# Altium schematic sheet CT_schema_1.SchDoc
size 486 x 344 mm
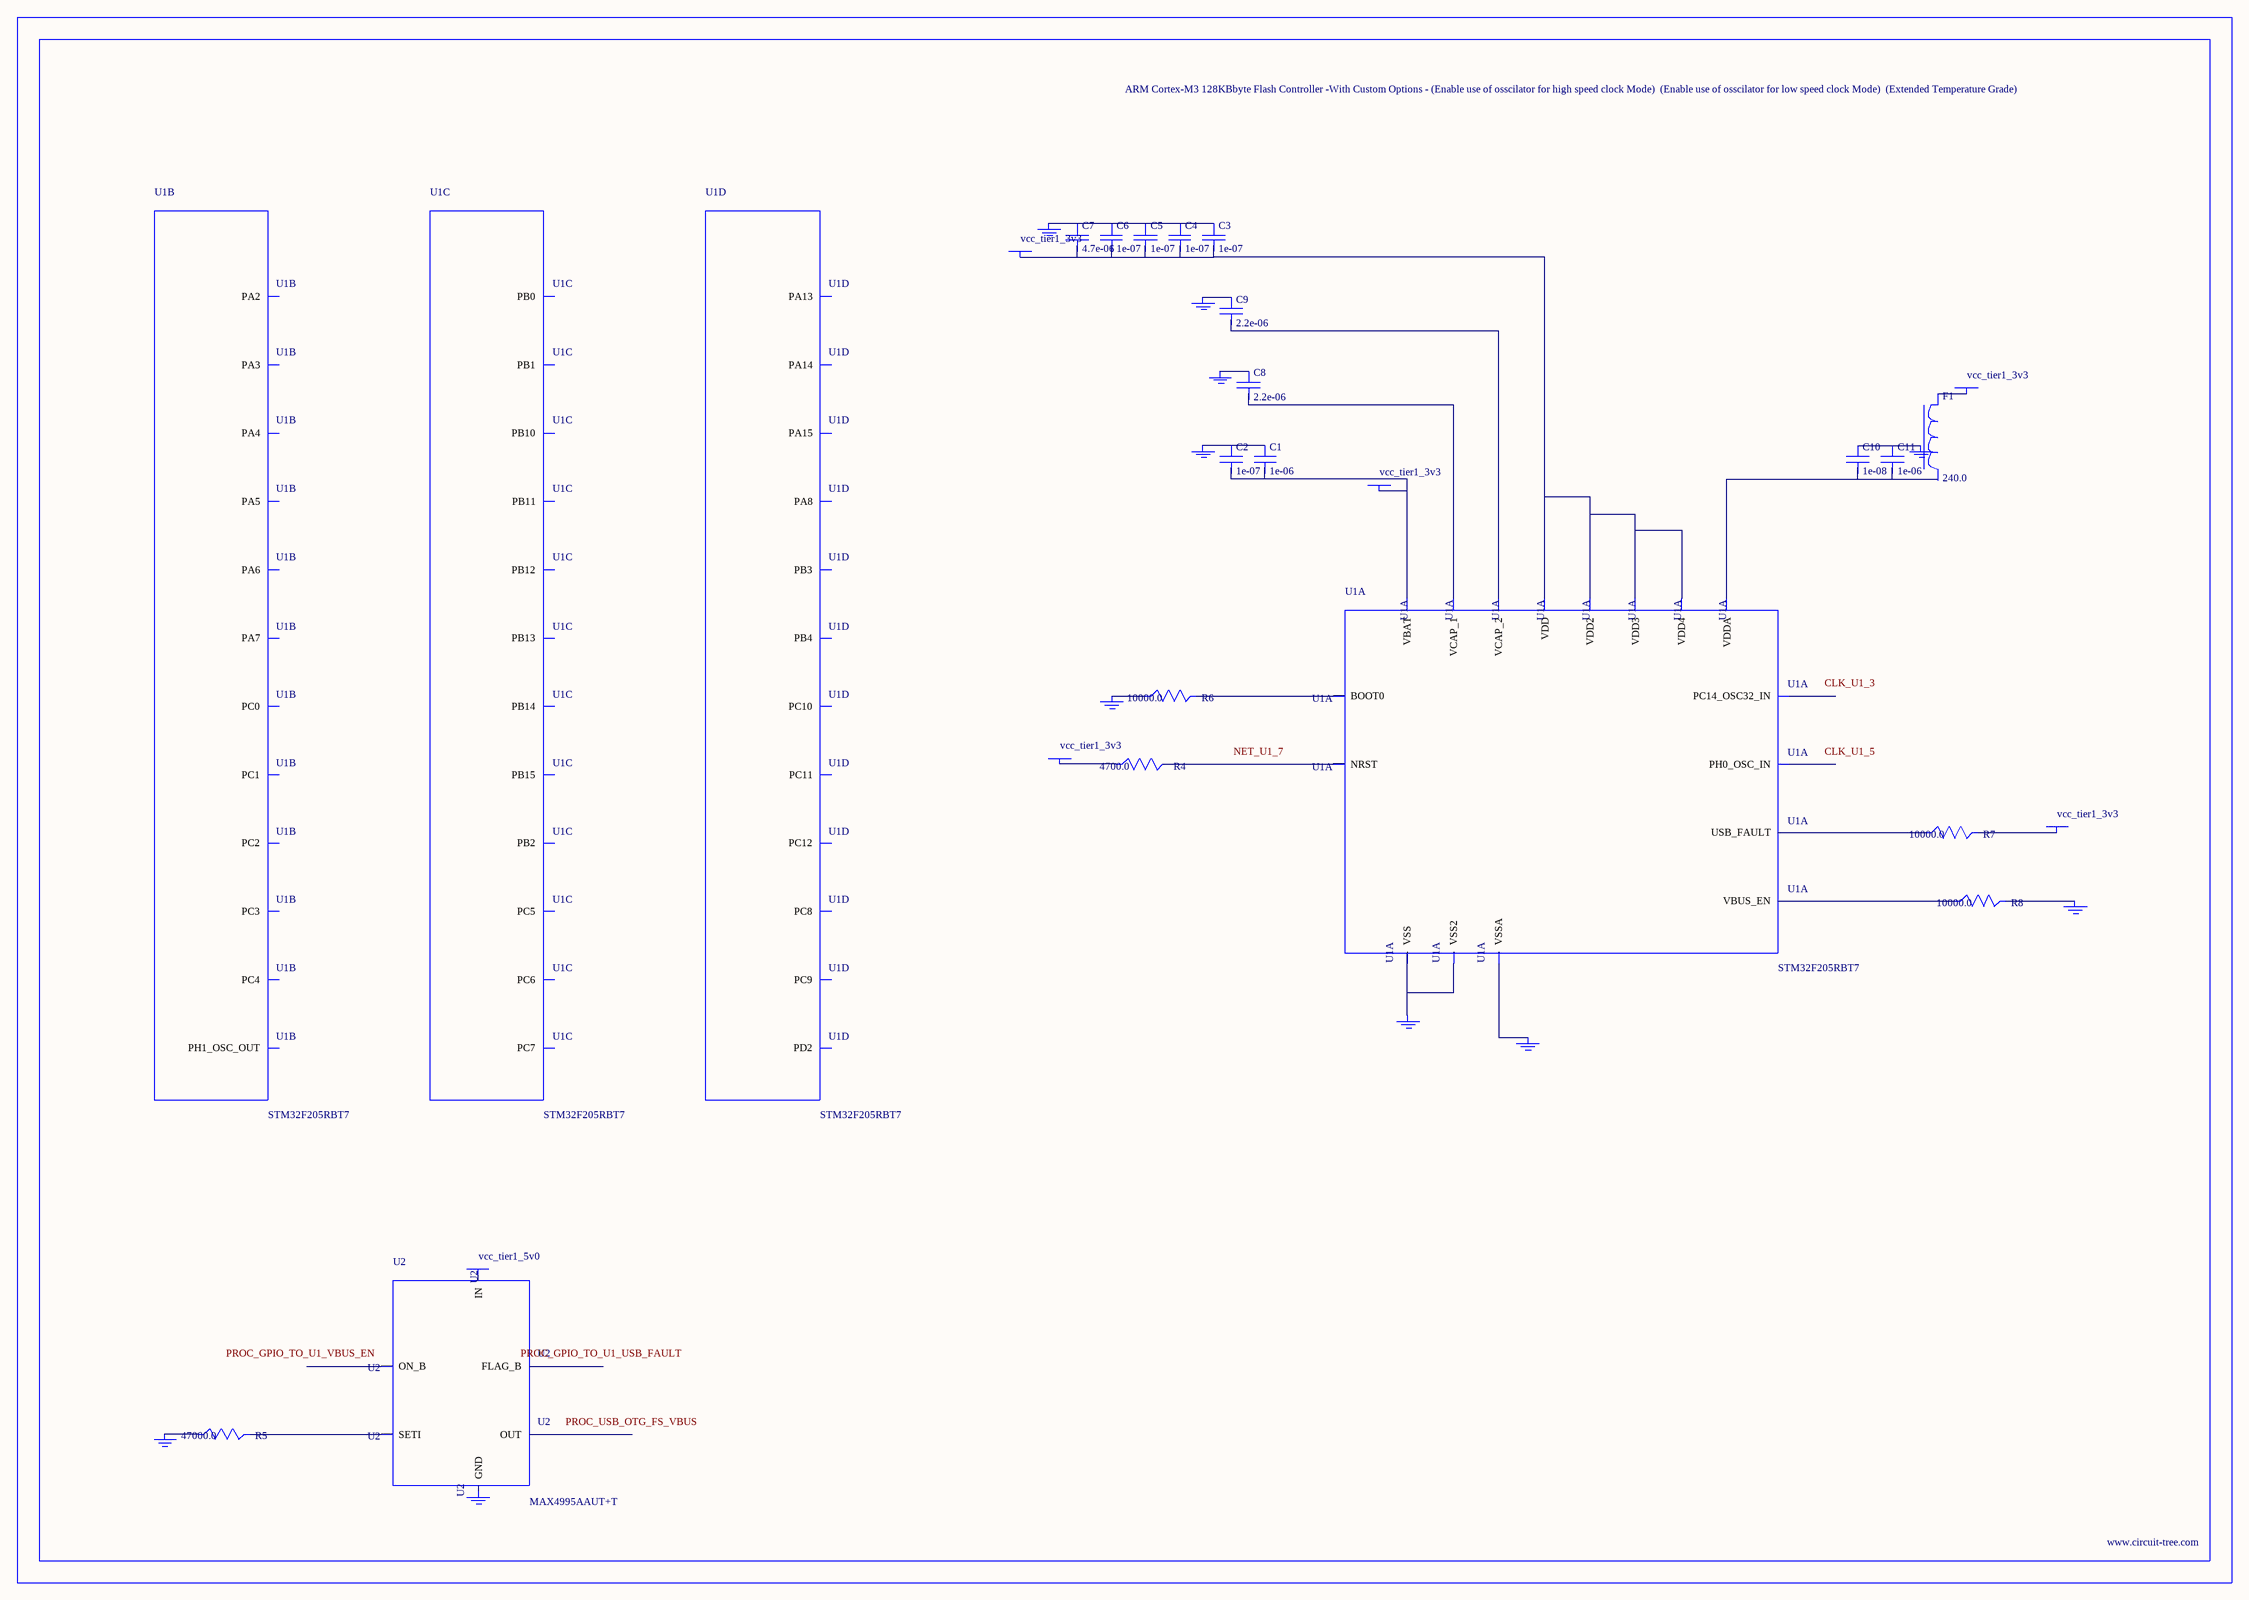
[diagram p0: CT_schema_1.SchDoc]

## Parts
BORDER0  (no value)
C1  1e-06  [C0603]
C2  1e-07  [C0603]
C3  1e-07  [C0603]
C4  1e-07  [C0603]
C5  1e-07  [C0603]
C6  1e-07  [C0603]
C7  4.7e-06  [C0603]
C8  2.2e-06  [C0603]
C9  2.2e-06  [C0603]
C10  1e-08  [C0603]
C11  1e-06  [C0603]
F1  240.0  [L0603]
GND_INSTANCE_0_0  (no value)
GND_INSTANCE_0_1  (no value)
GND_INSTANCE_0_2  (no value)
GND_INSTANCE_0_3  (no value)
GND_INSTANCE_0_4  (no value)
GND_INSTANCE_0_5  (no value)
GND_INSTANCE_0_6  (no value)
GND_INSTANCE_0_7  (no value)
GND_INSTANCE_0_8  (no value)
GND_INSTANCE_0_9  (no value)
GND_INSTANCE_0_10  (no value)
POWER_INSTANCE_0_0  vcc_tier1_3v3
POWER_INSTANCE_0_1  vcc_tier1_3v3
POWER_INSTANCE_0_2  vcc_tier1_3v3
POWER_INSTANCE_0_3  vcc_tier1_3v3
POWER_INSTANCE_0_4  vcc_tier1_3v3
POWER_INSTANCE_0_5  vcc_tier1_5v0
R4  4700.0  [R0603]
R5  47000.0  [R0603]
R6  10000.0  [R0603]
R7  10000.0  [R0603]
R8  10000.0  [R0603]
U1  STM32F205RBT7  [LQFP64]  (parts A,B,C,D of 7)
U2  MAX4995AAUT+T  [SOT-23-6]

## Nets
NetC1_1: C1.1 C2.1 GND_INSTANCE_0_0.0(GND)
NetC1_2: C1.2 C2.2 POWER_INSTANCE_0_0.0(PWR) U1.1(VBAT)
NetC3_1: C3.1 C4.1 C5.1 C6.1 C7.1 GND_INSTANCE_0_4.0(GND)
NetC3_2: C3.2 C4.2 C5.2 C6.2 C7.2 POWER_INSTANCE_0_3.0(PWR) U1.19(VDD) U1.32(VDD2) U1.48(VDD3) U1.64(VDD4)
NetC8_1: C8.1 GND_INSTANCE_0_5.0(GND)
NetC8_2: C8.2 U1.31(VCAP_1)
NetC9_1: C9.1 GND_INSTANCE_0_6.0(GND)
NetC9_2: C9.2 U1.47(VCAP_2)
NetC10_1: C10.1 C11.1 GND_INSTANCE_0_3.0(GND)
NetC10_2: C10.2 C11.2 U1.13(VDDA)
NetF1_1: F1.1 POWER_INSTANCE_0_2.0(PWR)
NetGND_INSTANCE_0_1_0: GND_INSTANCE_0_1.0(GND) R8.2
NetGND_INSTANCE_0_2_0: GND_INSTANCE_0_2.0(GND) U1.12(VSSA)
NetGND_INSTANCE_0_7_0: GND_INSTANCE_0_7.0(GND) R6.1
NetGND_INSTANCE_0_8_0: GND_INSTANCE_0_8.0(GND) U1.18(VSS) U1.63(VSS2)
NetGND_INSTANCE_0_9_0: GND_INSTANCE_0_9.0(GND) R5.1
NetPOWER_INSTANCE_0_1_0: POWER_INSTANCE_0_1.0(PWR) R7.2
NetPOWER_INSTANCE_0_4_0: POWER_INSTANCE_0_4.0(PWR) R4.1
NetR4_2: R4.2 U1.7(NRST)
NetR5_2: R5.2 U2.3(SETI)
NetR6_2: R6.2 U1.60(BOOT0)
NetR7_1: R7.1 U1.4(USB_FAULT)
NetR8_1: R8.1 U1.2(VBUS_EN)

Not connected (* = marked no-connect by the designer): F1 2; GND_INSTANCE_0_10 0(GND); POWER_INSTANCE_0_5 0(PWR); U1 3(PC14_OSC32_IN) 5(PH0_OSC_IN) 6(PH1_OSC_OUT) 8(PC0) 9(PC1) 10(PC2) 11(PC3) 16(PA2) 17(PA3) 20(PA4) 21(PA5) 22(PA6) 23(PA7) 24(PC4) 25(PC5) 26(PB0) 27(PB1) 28(PB2) 29(PB10) 30(PB11) 33(PB12) 34(PB13) 35(PB14) 36(PB15) 37(PC6) 38(PC7) 39(PC8) 40(PC9) 41(PA8) 46(PA13) 49(PA14) 50(PA15) 51(PC10) 52(PC11) 53(PC12) 54(PD2) 55(PB3) 56(PB4); U2 1(OUT) 2(GND) 4(ON_B) 5(IN) 6(FLAG_B)

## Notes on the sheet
- Labels drawn without touching a wire or pin: CLK_U1_3, CLK_U1_5, NET_U1_7, PROC_GPIO_TO_U1_USB_FAULT, PROC_GPIO_TO_U1_VBUS_EN, PROC_USB_OTG_FS_VBUS

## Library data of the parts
BORDER0 = BORDER_PAGE0
C1 C11 = C0603C105K3RACTU
C2-C6 = 06035C104K4Z2A
C7 = GRM188R6YA475KE15D
C8 C9 = C0603C225K8RACTU
C10 = 06035C103K4Z2A
F1 = Z0603C241ASMST
GND_INSTANCE_0_0-GND_INSTANCE_0_10 = GND
POWER_INSTANCE_0_0-POWER_INSTANCE_0_5 = PWR
R4 = RC0603JR-074K7L
R5 = RC0603JR-0747KL
R6-R8 = RC0603JR-0710KL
